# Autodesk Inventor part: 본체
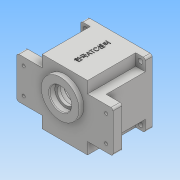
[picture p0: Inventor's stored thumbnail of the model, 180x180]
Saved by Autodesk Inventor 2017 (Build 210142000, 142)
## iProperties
Part Number: 본체
Material: 일반
Document SubType Name: Modeling
Designer: user
Density: 1 g/cm^3
Appearance: 기본값
Author: user
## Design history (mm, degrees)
sketch "스케치1"
  geometry: L1 (-70, -30)-(-70, 30); L2 (70, 30)-(70, -30); L3 (-33, -47)-(33, -47); L4 (33, 47)-(-33, 47); L5 (-70, 30)-(-33, 30); L6 (33, 30)-(70, 30); L7 (33, -47)-(33, -30); L8 (33, 30)-(33, 47); L9 (70, -30)-(33, -30); L10 (-33, 47)-(-33, 30); L11 (-33, -30)-(-33, -47); L12 (-33, -30)-(-70, -30); 1 further point
  constraints: 24 end point, 10 parallel, 4 perpendicular, 3 horizontal
  dimensions: "d0" = 140 distance of L1.end L2.start; "d1" = 60 distance of L1.start L1.end; "d2" = 66 distance of L4.end L4.start; "d3" = 94 distance of L4.start L3.end; "d4" = 140 distance of L2.end L1.start; "d5" = 66 distance of L3.start L3.end; "d6" = 37 distance of L2.end L7.end; "d7" = 37 distance of L11.start L1.start; "d8" = 17 distance of L6.start L4.start; "d9" = 33 horizontal distance of L6.start point (0, 0); "d10" = 30 vertical distance of L6.start point (0, 0); "d11" = 33 horizontal distance of point (0, 0) L3.start
extrude "돌출1" new body sketch "스케치1" distance "d12" = 13; taper "d13" = 0 deg
sketch "스케치3"
  geometry: L1 (-33, -47)-(33, -47); L2 (47, -30)-(47, 30); L3 (33, 47)-(-33, 47); L4 (-47, 30)-(-47, -30); L5 (-33, -30)-(-33, -47) reference; L6 (-33, 47)-(-33, 30) reference; L7 (-33, 30)-(-70, 30) reference; L8 (-70, -30)-(-33, -30) reference; L9 (-70, 30)-(-70, -30) reference; L10 (-70, -30)-(-33, -30) reference; L11 (-33, -30)-(-33, -47) reference; L12 (-33, -47)-(33, -47) reference; L13 (33, -47)-(33, -30) reference; L14 (33, -30)-(70, -30) reference; L15 (70, -30)-(70, 30) reference; L16 (70, 30)-(33, 30) reference; L17 (33, 30)-(33, 47) reference; L18 (33, 47)-(-33, 47) reference; L19 (-33, 47)-(-33, 30) reference; L20 (-33, 30)-(-70, 30) reference; 1 further point
  constraints: 9 point on line, 8 end point, 2 parallel, 1 horizontal, 1 perpendicular
  dimensions: "d17" = 94 distance between parallel lines of L4 L2; "d18" = 94 distance between parallel lines of L3 L1; "d19" = 14 distance from line of L4 L5.end
extrude "돌출3" join sketch "스케치3" distance "d20" = 67; taper "d21" = 0 deg
sketch "스케치4"
  geometry: L1 (-47, -47)-(47, -47); L2 (47, -47)-(47, 47); L3 (47, 47)-(-47, 47); L4 (-47, 47)-(-47, -47); L5 (-47, -47)-(47, 47); L6 (47, -47)-(-47, 47); 1 further point
  constraints: 12 end point, 2 midpoint, 2 parallel, 1 horizontal, 1 perpendicular
  dimensions: "d22" = 94 distance of L3.end L2.end; "d23" = 94 distance of L2.end L1.end
extrude "돌출4" join sketch "스케치4" distance "d24" = 10; taper "d25" = 0 deg
sketch "스케치5"
  geometry: C1 r 27.5 at (0, 11); 1 further point
  constraints: 1 centre point, 1 vertical alignment
  dimensions: "d26" = 55 diameter of C1; "d27" = 11 distance of point (0, 0) C1.centre
extrude "돌출5" join sketch "스케치5" distance "d28" = 7; taper "d29" = 0 deg
sketch "스케치6"
  geometry: C1 r 43 at (0, 0); 1 further point
  constraints: 1 centre point, 1 coincident
  dimensions: "d30" = 86 diameter of C1
extrude "돌출6" cut sketch "스케치6" distance "d31" = 9; taper "d32" = 0 deg
sketch "스케치7"
  geometry: C1 r 40 at (0, 0); 1 further point
  constraints: 1 centre point, 1 coincident
  dimensions: "d33" = 80 diameter of C1
extrude "돌출7" cut sketch "스케치7" distance "d34" = 62; taper "d35" = 0 deg
sketch "스케치8"
  geometry: C1 r 27.5 at (0, -11) reference; C2 r 21 at (0, -11); 1 further point
  constraints: 1 centre point, 1 coincident
  dimensions: "d36" = 42 diameter of C2
extrude "돌출8" join sketch "스케치8" distance "d37" = 7; taper "d38" = 0 deg
sketch "스케치9"
  geometry: C1 r 15 at (0, 20); C2 r 21 at (0, -11) reference; 1 further point
  constraints: 1 centre point, 1 vertical alignment
  dimensions: "d39" = 30 diameter of C1; "d40" = 20 distance of C1.centre point (0, 0)
extrude "돌출9" join sketch "스케치9" distance "d41" = 7; taper "d42" = 0 deg
sketch "스케치10"
  geometry: C1 r 27.5 at (0, 0) reference; C2 r 16 at (0, 0); 1 further point
  constraints: 1 centre point, 1 coincident
  dimensions: "d43" = 32 diameter of C2
extrude "돌출10" cut sketch "스케치10" distance "d44" = 8.3; taper "d45" = 0 deg
sketch "스케치11"
  geometry: C1 r 17.5 at (0, -11); A1 r 21 centre (0, -11) between (-8.978, 7.984) and (8.978, 7.984) reference; 1 further point
  constraints: 1 centre point, 1 coincident
  dimensions: "d46" = 35 diameter of C1
extrude "돌출11" cut sketch "스케치11" distance "d47" = 10; taper "d48" = 0 deg
sketch "스케치12"
  geometry: C1 r 17.5 at (0, 0) reference; C2 r 12.5 at (0, 0); 1 further point
  constraints: 1 centre point, 1 coincident
  dimensions: "d49" = 25 diameter of C2
extrude "돌출12" cut sketch "스케치12" distance "d50" = 10; taper "d51" = 0 deg
sketch "스케치13"
  geometry: C1 r 11 at (0, 20); A1 r 15 centre (0, 20) between (8.978, 7.984) and (-8.978, 7.984) reference; 1 further point
  constraints: 1 centre point, 1 coincident
  dimensions: "d52" = 22 diameter of C1
extrude "돌출13" cut sketch "스케치13" distance "d53" = 7; taper "d54" = 0 deg
sketch "스케치14"
  geometry: C1 r 11 at (0, 0) reference; C2 r 9.5 at (0, 0); 1 further point
  constraints: 1 centre point, 1 coincident
  dimensions: "d55" = 19 diameter of C2
extrude "돌출14" cut sketch "스케치14" distance "d56" = 3; taper "d57" = 0 deg
fillet "모깎기1" dims "d58" = 3
chamfer "모따기1" distance "d59" = 0.8; stored, may be unused: second distance "d60" = 2, angle "d61" = 60 deg
chamfer "모따기2" distance "d62" = 1; stored, may be unused: second distance "d63" = 2, angle "d64" = 45 deg
fillet "모깎기2" dims "d65" = 3
chamfer "모따기3" distance "d66" = 1; stored, may be unused: second distance "d67" = 2, angle "d68" = 45 deg
sketch "스케치15"
  geometry: L1 (36, 4)-(36.332, 4); L2 (36, -4)-(36.332, -4); A1 r 4 centre (36, 0) between (36, 4) and (36, -4); A2 r 40 centre (0, 0) between (39.799, 4) and (39.799, -4) reference; A3 r 40 centre (0, 0) between (39.278, 7.568) and (39.278, -7.568); A4 r 3 centre (36.332, 7) between (36.332, 4) and (39.278, 7.568); A5 r 3 centre (36.332, -7) between (39.278, -7.568) and (36.332, -4); 1 further point
  constraints: 12 point on circle, 6 tangent, 4 centre point, 4 end point, 2 equal radius, 2 horizontal, 2 point on line, 2 vertical alignment, 1 coincident, 1 horizontal alignment
  dimensions: "d69" = 8 diameter of A1; "d70" = 36 distance of point (0, 0) A1.centre; "d71" = 3 radius of A4 (derived)
extrude "돌출15" join sketch "스케치15" stored distance "d72" = 3; taper "d73" = 0 deg
sketch "스케치16"
  geometry: A1 r 4 centre (36, 0) between (36, 4) and (36, -4) reference; A2 r 4 centre (-36, 0) between (-36, -4) and (-36, 4) reference; 1 further point
hole "구멍1" sketch "스케치16" at (-36, 0), (36, 0) diameter "d74" = 3.242; stored, may be unused: countersink angle "d78" = 90 deg, drill point angle "d80" = 118 deg; dims "d75" = 7, "d76" = 4, "d77" = 2, "d79" = 9
sketch "스케치17"
  geometry: 2 further points
  dimensions: "d81" = 40 horizontal distance of point (-40, 40) point (0, 0); "d82" = 40 horizontal distance of point (-40, 40) point (0, 0)
hole "구멍2" sketch "스케치17" at (-40, 40) diameter "d83" = 7; stored, may be unused: countersink angle "d87" = 90 deg, drill point angle "d89" = 118 deg; dims "d84" = 7, "d85" = 4, "d86" = 2, "d88" = 9
sketch "스케치18"
  geometry: 2 further points
  dimensions: "d96" = 19 vertical distance of point (-60, 19) point (0, 0); "d97" = 60 horizontal distance of point (0, 0) point (-60, 19)
hole "구멍3" sketch "스케치18" at (-60, 19) diameter "d98" = 4.5; stored, may be unused: countersink angle "d102" = 90 deg, drill point angle "d104" = 118 deg; dims "d99" = 7, "d100" = 10, "d101" = 5, "d103" = 9
chamfer "모따기4" distance "d111" = 1; stored, may be unused: second distance "d112" = 2, angle "d113" = 45 deg
fillet "모깎기3" dims "d114" = 3
sketch "스케치19" dims "d0" = 140, "d1" = 60, "d2" = 66, "d3" = 94, "d4" = 140, "d5" = 66, "d6" = 37, "d7" = 37, "d8" = 17, "d9" = 33, "d10" = 30, "d11" = 33
  geometry: L1 (-11, 80)-(77, 80) reference; L2 (0, 0)-(66, 0) reference; 3 further points
  constraints: 1 midpoint, 1 vertical alignment, 1 other
  dimensions: "d115" = 40 distance from line of L1 point (33, 40)
feature "엠보싱1" sketch "스케치19" dims "d0" = 140, "d1" = 60, "d2" = 66, "d3" = 94, "d4" = 140, "d5" = 66, "d6" = 37, "d7" = 37, "d8" = 17, "d9" = 33, "d10" = 30, "d11" = 33, "d116" = 0.5, "d117" = 0
node "솔리드1"
mirror "미러1"
pattern_linear "직사각형 패턴1" dims "d92" = 80, "d95" = 80
pattern_linear "직사각형 패턴2" dims "d107" = 120, "d110" = 38
node "투영된 루프1"
